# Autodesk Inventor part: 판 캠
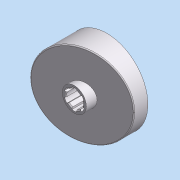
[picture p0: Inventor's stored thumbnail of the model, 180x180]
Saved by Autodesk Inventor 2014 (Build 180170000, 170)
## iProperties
Created: 2012-05
Part Number: 판 캠
Document SubType Name: 모델링
Designer: SeoGD™
Material: 강철
Appearance: 알루미늄 - 평지
Density: 1 g/cm^3
변환 표준: STEP AP214IS
파일 이름: C:\Users\SeoGD\Desktop\?쒗뿕\??stp
전처리기: Build: 253, Release: 2010 SP1 - Date: Wed 07/29/2009
전송 단위: 밀리미터
불확실성: 0.01
Author: SeoGD™
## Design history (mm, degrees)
node "작업 평면4"
sketch "스케치1"
  geometry: C1 r 44.5 at (0, 0); 1 further point
  constraints: 1 centre point, 1 coincident
  dimensions: "d25" = 89 diameter of C1
extrude "돌출1" new body sketch "스케치1" distance "d1" = 40; taper "d2" = 0 deg
sketch "스케치2"
  geometry: L1 (-44.5, 15)-(44.5, 38.847); L2 (-44.5, 0)-(-44.5, 40) reference; L3 (-44.5, 40)-(44.5, 40) reference; L4 (44.5, 0)-(44.5, 40) reference; 1 further point
  constraints: 2 end point, 2 point on line
  dimensions: "d26" = 15 distance of L2.start L1.start; "d27" = 75 deg angle of L1 L2
extrude "돌출2" cut sketch "스케치2" stored distance "d5" = 40; taper "d6" = 0 deg
node "작업 평면1"
sketch "스케치3"
  geometry: C1 r 13 at (0, 0); 1 further point
  constraints: 1 centre point, 1 coincident
  dimensions: "d9" = 26 diameter of C1
extrude "돌출3" join sketch "스케치3" distance "d10" = 38; taper "d11" = 0 deg
hole "구멍1" diameter "d14" = 18; stored, may be unused: countersink angle "d18" = 90 deg, drill point angle "d20" = 118 deg; dims "d12" = 10, "d13" = 10, "d15" = 6, "d16" = 4, "d17" = 2, "d19" = 8
feature "쉘2" dims "d29" = 5
sketch "스케치6"
  geometry: C1 r 17.5 at (0, 0); C2 r 14 at (0, 0) reference; 1 further point
  constraints: 1 centre point, 1 coincident
  dimensions: "d28" = 35 diameter of C1
extrude "돌출4" join sketch "스케치6" stored distance "d30" = 38; taper "d31" = 0 deg
fillet "모깎기1" dims "d32" = 3
chamfer "모따기1" distance "d21" = 1; stored, may be unused: second distance "d22" = 2, angle "d23" = 45 deg
sketch "스케치7"
  geometry: L1 (-12.374, 12.374)-(-27.931, 27.931); A1 r 39.5 centre (0, 0) between (-27.931, 27.931) and (0, 39.5) reference; 2 further points
  constraints: 2 end point, 2 point on circle, 1 point on line, 1 vertical alignment, 2 other
  dimensions: "d33" = 45 deg dimension on point (0, 0) L1.start A1.end
feature "리브1" sketch "스케치7" dims "d34" = 5, "d35" = 1, "d36" = 0
fillet "모깎기2" dims "d37" = 3
sketch "스케치8"
  geometry: L1 (2.5, 10.712)-(2.5, 8.646); L2 (-2.5, 10.712)-(-2.5, 8.646); A1 r 11 centre (0, 0) between (2.5, 10.712) and (-2.5, 10.712); A2 r 9 centre (0, 0) between (2.5, 8.646) and (-2.5, 8.646) reference; 1 further point
  constraints: 4 end point, 4 point on circle, 2 parallel, 1 centre point, 1 coincident, 1 vertical
  dimensions: "d41" = 22 diameter of A1; "d42" = 5 distance between parallel lines of L1 L2
extrude "돌출5" cut sketch "스케치8" stored distance "d43" = 38; taper "d44" = 0 deg
fillet "모깎기3" dims "d48" = 1
node "솔리드1"
node "솔리드 본체"
node "곡면 본체"
pattern_circular "원형 패턴1" dims angle "d39" = 360 deg
pattern_circular "원형 패턴2" dims angle "d46" = 360 deg
node "솔리드2"
